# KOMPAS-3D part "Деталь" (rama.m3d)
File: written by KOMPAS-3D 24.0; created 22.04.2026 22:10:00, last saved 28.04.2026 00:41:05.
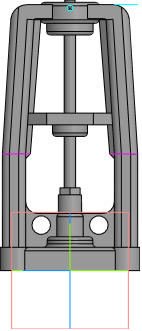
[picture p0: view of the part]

Document properties: Автор: mrdid; Полное имя файла: C:\Работа\ГОТОВЫЕ ИСХОДНИКИ\VSO2130M-F-S Клапан запорный сильфонный DN.ru Ду15-100 Ру40\исходные материалы\DN20\rama.m3d

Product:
- Part/product: Деталь
    Масса: 0.702168

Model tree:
1. Эскиз:2  (with: Ребро.Элемент выдавливания:14)
2. Элемент выдавливания:1
     Расстояние 1 = 10
3. Эскиз:3  (with: Грань.Элемент выдавливания:1, Ребро.Элемент выдавливания:1)
4. Элемент выдавливания:2
     Расстояние 2 = 10
5. Эскиз:4  (with: Грань.Элемент выдавливания:1)
6. Элемент выдавливания:3
     Расстояние 1 = 4.5
7. Эскиз:5  (with: Грань.Элемент выдавливания:3, Ребро.Элемент выдавливания:3)
8. Элемент выдавливания:4
     Расстояние 1 = 10
9. Эскиз:6  (with: Грань.Элемент выдавливания:1, Ребро.Элемент выдавливания:1)
10. Элемент выдавливания:5
     Расстояние 1 = 40
11. Эскиз:23  (with: Грань.Элемент выдавливания:4, Ребро.Элемент выдавливания:4)
12. Элемент выдавливания:21
     Расстояние 1 = 11
13. Эскиз:7  (with: Грань.Элемент выдавливания:21, Ребро.Элемент выдавливания:3)
14. Элемент выдавливания:6
     Расстояние 2 = 3
15. Эскиз:8  (with: Грань.Элемент выдавливания:5, Ребро.Элемент выдавливания:5)
16. Смещенная плоскость:1  (with: Грань.Элемент выдавливания:5)
17. Эскиз:9
18. Элемент по сечениям:1
19. Элемент по сечениям:2
20. Эскиз:10
21. Элемент выдавливания:8
     Расстояние 2 = 6
22. Эскиз:11  (with: Грань.Элемент выдавливания:8, Ребро.Элемент выдавливания:3)
23. Элемент выдавливания:9  (with: Грань.Элемент выдавливания:8)
     Расстояние 1 = 1; Расстояние 2 = 8; Смещение 2 = 2
24. Эскиз:12  (with: Грань.Элемент выдавливания:9, Ребро.Элемент выдавливания:9)
25. Элемент выдавливания:10
     Расстояние 1 = 5
26. Эскиз:13  (with: Грань.Элемент выдавливания:21, Ребро.Элемент выдавливания:3)
27. Элемент выдавливания:11  (with: Грань.Элемент выдавливания:10)
     Расстояние 1 = 65.488
28. Смещенная плоскость:2  (with: Грань.Элемент выдавливания:21)
29. Эскиз:14  (with: Ребро.Элемент по сечениям:2, Ребро.Элемент по сечениям:1)
30. Элемент выдавливания:12
     Расстояние 1 = 5
31. Эскиз:15  (with: Грань.Элемент выдавливания:12, Ребро.Элемент выдавливания:3)
32. Элемент выдавливания:13
     Расстояние 1 = 5
33. Эскиз:16  (with: Ребро.Элемент выдавливания:5, Ребро.Элемент выдавливания:1, Ребро.Элемент выдавливания:4)
34. Элемент выдавливания:14
     Расстояние 1 = 4
35. Элемент выдавливания:15
     Расстояние 1 = 2
36. Эскиз:17  (with: Ребро.Элемент выдавливания:5, Ребро.Элемент выдавливания:14)
37. Элемент выдавливания:16
     Расстояние 1 = 30
38. Скругление:1  (with: Ребро.Элемент выдавливания:1, Ребро.Элемент выдавливания:3)
     Радиус = 1.5
39. Скругление:2  (with: Ребро.Элемент выдавливания:9, Ребро.Элемент выдавливания:10, Ребро.Элемент выдавливания:13, Ребро.Элемент выдавливания:4)
40. Эскиз:18  (with: Грань.Элемент выдавливания:9)
41. Элемент выдавливания:17
     Расстояние 1 = 1
42. Скругление:3  (with: Ребро.Элемент по сечениям:2, Ребро.Элемент по сечениям:1)
     Радиус = 7
43. Скругление:4  (with: Ребро.Элемент выдавливания:8)
     Радиус = 0.5
44. Скругление:5  (with: Ребро.Элемент выдавливания:14)
     Радиус = 5
45. Эскиз:19  (with: Ребро.Элемент выдавливания:17)
46. Элемент выдавливания:18
47. Смещенная плоскость:3  (with: Грань.Элемент выдавливания:18)
     Расстояние = 2
48. Эскиз:20  (with: Ребро.Элемент выдавливания:18)
49. Элемент выдавливания:19
     Расстояние 2 = 0.2
50. Скругление:6  (with: Ребро.Элемент выдавливания:18)
     Радиус = 1
51. Эскиз:21  (with: Ребро.Элемент выдавливания:19)
52. Элемент выдавливания:20
     Расстояние 1 = 10
53. Скругление:7  (with: Ребро.Элемент по сечениям:2, Ребро.Элемент выдавливания:5, Ребро.Элемент по сечениям:1)
     Радиус = 3
54. Фаска:1  (with: Ребро.Элемент по сечениям:1, Ребро.Элемент по сечениям:2)
     Угол = 45; Длина 1 = 2; Длина 2 = 2
55. Массив по концентрической сетке:1  (with: Элемент выдавливания:2, Эскиз:3)  (4 pattern instances)
     Шаг 2 = 360

Expressions: v249/2; DN/2
Referenced files in C:\Работа\ГОТОВЫЕ ИСХОДНИКИ\VSO2130M-F-S Клапан запорный сильфонный DN.ru Ду15-100 Ру40\исходные материалы\DN20\: VSO2130M-F-S Клапан запорный DN.ru Ду20 Ру40.a3d
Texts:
  DN+5
  DN-5
  Клапан запорный сильфонный DN.ru
  Ось Y.Начало координат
